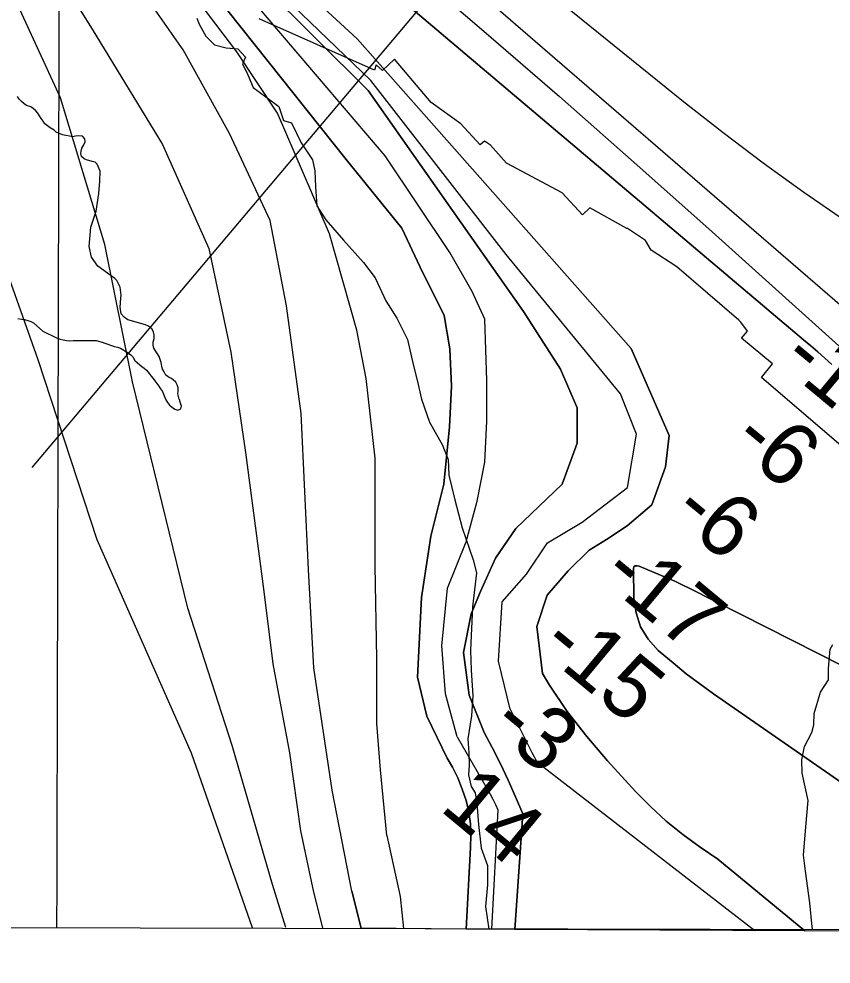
# Model space of a CAD drawing. Extents: x 3172231 to 3210228, y 940198 to 965780.
# Drawn here: x 3192098 to 3192968, y 945652 to 946666 of the extents above; entities that cross this region are included whole.
import ezdxf

# ---------------------------------------------------------------- set-up
doc = ezdxf.new("R2010")
doc.units = 0
for name, color, linetype in [('V-GRID-FRAM', 7, 'Continuous'), ('V-GRID-MAJR', 7, 'Continuous'), ('V-RIVR-EDGE', 7, 'Continuous'), ('V-RIVR-RANG', 7, 'Continuous'), ('V-RRAP-RVMT', 7, 'Continuous'), ('V-TOPO-DPTH', 7, 'Continuous'), ('V-TOPO-MAJR', 7, 'Continuous'), ('V-TOPO-MINR', 7, 'Continuous'), ('V-TOPO-SHOR', 7, 'Continuous'), ('V-TOPO-WATR', 7, 'Continuous')]:
    doc.layers.add(name, color=color, linetype=linetype)

msp = doc.modelspace()

# ---------------------------------------------------------------- linework, layer by layer
at = {"layer": 'V-GRID-FRAM'}
msp.add_lwpolyline([(3176539.592, 963919.479), (3207827.662, 963842.116), (3207790.623, 945652.442), (3176486.679, 945729.845), (3176539.592, 963919.479)], dxfattribs=at)
at = {"layer": 'V-GRID-MAJR'}
msp.add_spline([(3192138.65, 945691.144), (3192153.634, 951750.897), (3192168.626, 957814.116), (3192183.618, 963877.385), (3192183.626, 963880.798)], degree=3, dxfattribs=at)
at = {"layer": 'V-RIVR-EDGE'}
for points in [[(3192288.478, 946666.525), (3192291.056, 946660.295), (3192298.284, 946647.311), (3192307.597, 946637.953), (3192320.036, 946634.811), (3192332.48, 946633.742), (3192340.756, 946624.905), (3192337.626, 946617.652), (3192343.302, 946605.71), (3192348.973, 946592.212), (3192362.433, 946582.325), (3192376.41, 946571.918), (3192381.559, 946556.865), (3192389.851, 946554.251), (3192400.17, 946532.962), (3192412.572, 946514.78), (3192415.136, 946502.845), (3192415.612, 946485.729), (3192417.118, 946465.499), (3192426.935, 946450.435), (3192445.551, 946428.607), (3192467.274, 946404.697), (3192479.68, 946388.07), (3192491.029, 946363.667), (3192502.911, 946344.967), (3192514.265, 946322.119), (3192520.421, 946295.136), (3192524.529, 946278.53), (3192529.147, 946258.292), (3192537.902, 946233.376), (3192551.327, 946209.487), (3192558.029, 946193.393), (3192558.507, 946176.796), (3192565.184, 946150.329), (3192572.888, 946120.23), (3192584.732, 946085.972), (3192588.328, 946071.96), (3192584.089, 946035.667), (3192581.899, 945988.996), (3192582.365, 945967.732), (3192584.372, 945940.24), (3192582.762, 945918.461), (3192579.071, 945894.095), (3192580.071, 945879.053), (3192580.557, 945865.567), (3192579.494, 945855.197), (3192582.575, 945842.743), (3192586.707, 945835.991), (3192588.753, 945824.576)], [(3192948.613, 945689.141), (3192947.997, 945692.352), (3192945.439, 945718.247), (3192940.935, 945752.012), (3192938.684, 945769.386), (3192941.052, 945799.529), (3192943.744, 945827.706), (3192937.262, 945857.215), (3192936.97, 945871.307), (3192939.627, 945885.72), (3192947.529, 945900.775), (3192949.843, 945908.962), (3192950.201, 945921.086), (3192956.812, 945944.009), (3192965.365, 945957.096), (3192965.395, 945969.221), (3192967.085, 945990.19), (3192970.046, 945995.099)], [(3192588.753, 945824.576), (3192590.254, 945802.271), (3192593.303, 945776.851), (3192599.999, 945758.164), (3192599.948, 945737.42), (3192597.815, 945714.087), (3192601.342, 945689.999)]]:
    msp.add_lwpolyline(points, dxfattribs=at)
at = {"layer": 'V-RIVR-RANG'}
msp.add_line((3192112.067, 946184.869), (3192859.884, 947071.645), dxfattribs=at)
at = {"layer": 'V-RRAP-RVMT'}
for p, q in [((3192478.821, 946610.848), (3192355.33, 946665.852)), ((3192480.808, 946616.733), (3192478.821, 946610.848)), ((3192487.36, 946610.543), (3192480.808, 946616.733)), ((3192500.377, 946622.817), (3192487.36, 946610.543)), ((3192539.838, 946576.049), (3192500.377, 946622.817)), ((3192571.316, 946553.328), (3192539.838, 946576.049)), ((3192592.062, 946530.656), (3192571.316, 946553.328)), ((3192596.835, 946534.908), (3192592.062, 946530.656)), ((3192603.206, 946530.31), (3192596.835, 946534.908)), ((3192620.408, 946511.321), (3192603.206, 946530.31)), ((3192680.002, 946479.313), (3192620.408, 946511.321)), ((3192701.88, 946455.943), (3192680.002, 946479.313)), ((3192709.653, 946463.137), (3192701.88, 946455.943)), ((3192749.343, 946441.175), (3192709.653, 946463.137)), ((3192749.941, 946441.093), (3192749.343, 946441.175)), ((3192769.397, 946428.144), (3192749.941, 946441.093)), ((3192775.263, 946417.873), (3192769.397, 946428.144)), ((3192802.884, 946399.94), (3192775.263, 946417.873)), ((3192869.381, 946342.909), (3192802.884, 946399.94)), ((3192871.433, 946340.598), (3192869.381, 946342.909)), ((3192878.627, 946331.194), (3192871.433, 946340.598)), ((3192872.105, 946323.62), (3192878.627, 946331.194)), ((3192905.45, 946295.909), (3192872.105, 946323.62)), ((3192893.825, 946281.26), (3192905.45, 946295.909)), ((3192999.594, 946190.219), (3192893.825, 946281.26))]:
    msp.add_line(p, q, dxfattribs=at)
at = {"layer": 'V-TOPO-DPTH'}
for points in [[(3192099.681, 947031.915), (3192938.779, 946321.755), (3192946.371, 946315.27), (3192953.923, 946308.738), (3192961.414, 946302.136), (3192968.865, 946295.488)], [(3192968.865, 946295.488), (3192961.414, 946302.136), (3192953.923, 946308.738), (3192946.371, 946315.27), (3192938.779, 946321.755), (3192099.681, 947031.915)], [(3192125.015, 946953.462), (3192460.326, 946644.437), (3192753.916, 946312.397), (3192794.718, 946219.197), (3192790.938, 946185.676), (3192775.977, 946144.723), (3192749.876, 946122.415), (3192727.511, 946107.551), (3192708.876, 946096.406), (3192686.499, 946074.092), (3192664.115, 946048.052), (3192652.89, 946014.543), (3192658.947, 945963.859)], [(3192658.947, 945963.859), (3192652.89, 946014.543), (3192664.115, 946048.052), (3192686.499, 946074.092), (3192708.876, 946096.406), (3192727.511, 946107.551), (3192749.876, 946122.415), (3192775.977, 946144.723), (3192790.938, 946185.676), (3192794.718, 946219.197), (3192753.916, 946312.397), (3192460.326, 946644.437), (3192125.015, 946953.462)], [(3192556.965, 945873.249), (3192535.012, 945918.306), (3192525.143, 945960.083), (3192529.261, 946045.586), (3192539.308, 946111.193), (3192553.314, 946166.851), (3192559.38, 946228.487), (3192561.44, 946272.233), (3192559.519, 946312.008), (3192553.616, 946347.813), (3192527.864, 946399.56), (3192508.058, 946441.353), (3192448.554, 946515.031), (3192238.314, 946779.866), (3192074.996, 946940.791)], [(3192074.996, 946940.791), (3192238.314, 946779.866), (3192448.554, 946515.031), (3192508.058, 946441.353), (3192527.864, 946399.56), (3192553.616, 946347.813), (3192559.519, 946312.008), (3192561.44, 946272.233), (3192559.38, 946228.487), (3192553.314, 946166.851), (3192539.308, 946111.193), (3192529.261, 946045.586), (3192525.143, 945960.083), (3192535.012, 945918.306), (3192556.965, 945873.249)], [(3192596.457, 945900.913), (3192580.371, 945940.634), (3192574.484, 945986.382), (3192582.504, 946028.129), (3192592.482, 946051.975), (3192608.442, 946087.744), (3192630.358, 946119.525), (3192680.127, 946167.168), (3192696.1, 946210.891), (3192696.163, 946248.674), (3192678.345, 946290.465), (3192638.696, 946352.178), (3192581.193, 946433.806), (3192472.136, 946589.099), (3192245.929, 946814.188), (3192105.596, 946941.56)], [(3192105.596, 946941.56), (3192245.929, 946814.188), (3192472.136, 946589.099), (3192581.193, 946433.806), (3192638.696, 946352.178), (3192678.345, 946290.465), (3192696.163, 946248.674), (3192696.1, 946210.891), (3192680.127, 946167.168), (3192630.358, 946119.525), (3192608.442, 946087.744), (3192592.482, 946051.975), (3192582.504, 946028.129), (3192574.484, 945986.382), (3192580.371, 945940.634), (3192596.457, 945900.913)], [(3192454.597, 945730.763), (3192433.513, 945838.931), (3192413.857, 945970.211), (3192408.07, 946075.617), (3192400.398, 946242.672), (3192384.69, 946358.038), (3192366.954, 946449.543), (3192323.384, 946543.08), (3192273.844, 946632.65), (3192148.926, 946811.832), (3192048.178, 946936.112)], [(3192514.85, 946722.415), (3192596.158, 946652.773), (3192677.068, 946582.674), (3192757.379, 946511.89), (3192837.292, 946440.65), (3192980.139, 946312.212)], [(3192514.85, 946722.415), (3192596.158, 946652.773), (3192677.068, 946582.674), (3192757.379, 946511.89), (3192837.292, 946440.65), (3192980.139, 946312.212)], [(3193145.537, 945888.667), (3192816.049, 946055.524), (3192808.497, 946059.238), (3192800.889, 946062.833), (3192793.2, 946066.249), (3192785.456, 946069.546), (3192762.405, 946079.042), (3192760.407, 946079.509), (3192758.365, 946079.32), (3192756.889, 946078.336), (3192756.338, 946076.65), (3192756.928, 946044.903), (3192759.303, 946028.921), (3192764.055, 946014.045), (3192772.372, 946000.827), (3192783.065, 945988.714), (3192784.988, 945987.033), (3192798.885, 945975.27), (3192813.024, 945963.816), (3192827.526, 945952.826), (3192842.27, 945942.144), (3193028.61, 945812.751)], [(3193028.61, 945812.751), (3192842.27, 945942.144), (3192827.526, 945952.826), (3192813.024, 945963.816), (3192798.885, 945975.27), (3192784.988, 945987.033), (3192783.065, 945988.714), (3192772.372, 946000.827), (3192764.055, 946014.045), (3192759.303, 946028.921), (3192756.928, 946044.903), (3192756.338, 946076.65), (3192756.889, 946078.336), (3192758.365, 946079.32), (3192760.407, 946079.509), (3192762.405, 946079.042), (3192785.456, 946069.546), (3192793.2, 946066.249), (3192800.889, 946062.833), (3192808.497, 946059.238), (3192816.049, 946055.524), (3193145.537, 945888.667)], [(3192658.947, 945963.859), (3192666.543, 945951.383), (3192685.533, 945923.18), (3192706.414, 945896.347), (3192728.556, 945870.428), (3192758.571, 945837.649), (3192774.681, 945821.255), (3192791.495, 945805.676), (3192809.363, 945791.318), (3192827.934, 945777.775), (3192847.033, 945764.842), (3192939.958, 945688.192)], [(3192939.958, 945688.192), (3192847.033, 945764.842), (3192827.934, 945777.775), (3192809.363, 945791.318), (3192791.495, 945805.676), (3192774.681, 945821.255), (3192758.571, 945837.649), (3192728.556, 945870.428), (3192706.414, 945896.347), (3192685.533, 945923.18), (3192666.543, 945951.383), (3192658.947, 945963.859)], [(3192939.958, 945688.192), (3192629.237, 945689.446), (3192637.741, 945813.497), (3192630.198, 945831.613), (3192622.281, 945849.557), (3192613.802, 945867.242), (3192604.948, 945884.755), (3192596.457, 945900.913)], [(3192596.457, 945900.913), (3192604.948, 945884.755), (3192613.802, 945867.242), (3192622.281, 945849.557), (3192630.198, 945831.613), (3192637.741, 945813.497), (3192629.237, 945689.446)], [(3192629.237, 945689.446), (3192577.139, 945690.059), (3192581.784, 945777.451), (3192582.244, 945790.242), (3192581.757, 945802.943), (3192579.852, 945815.51), (3192577.002, 945827.988), (3192572.925, 945840.175), (3192568.197, 945852.071), (3192562.493, 945863.531), (3192556.965, 945873.249)], [(3192556.965, 945873.249), (3192562.493, 945863.531), (3192568.197, 945852.071), (3192572.925, 945840.175), (3192577.002, 945827.988), (3192579.852, 945815.51), (3192581.757, 945802.943), (3192582.244, 945790.242), (3192581.784, 945777.451), (3192577.139, 945690.059)], [(3192577.139, 945690.059), (3192464.738, 945690.822), (3192454.597, 945730.763)], [(3193216.424, 945687.024), (3192939.958, 945688.192)]]:
    msp.add_lwpolyline(points, dxfattribs=at)
at = {"layer": 'V-TOPO-MAJR'}
for points in [[(3191965.03, 946881.133), (3192003.878, 946837.926), (3192011.775, 946806.095), (3192015.704, 946778.248), (3192015.631, 946734.499), (3192017.539, 946686.769), (3192043.148, 946549.513), (3192070.782, 946434.128), (3192118.261, 946300.812), (3192181.541, 946107.812), (3192282.525, 945878.955), (3192347.711, 945691.839)], [(3192985.427, 946352.41), (3192545.757, 946733.188)]]:
    msp.add_lwpolyline(points, dxfattribs=at)
at = {"layer": 'V-TOPO-MINR'}
for points in [[(3192167.133, 947097.133), (3192810.081, 946577.224), (3192852.443, 946543.901), (3192895.379, 946511.356), (3192939.175, 946479.978), (3192983.545, 946449.379)], [(3192099.681, 947031.915), (3192938.779, 946321.755), (3192946.371, 946315.27), (3192953.923, 946308.738), (3192961.414, 946302.136), (3192968.865, 946295.488)], [(3192624.36, 945925.872), (3192611.871, 945977.359), (3192615.7, 946040.682), (3192641.813, 946070.441), (3192664.209, 946103.931), (3192701.479, 946126.221), (3192749.945, 946163.393), (3192759.718, 946220.728), (3192742.666, 946263.987), (3192620.044, 946413.203), (3192475.145, 946599.709), (3192289.277, 946778.832), (3192107.839, 946954.941)], [(3192658.947, 945963.859), (3192652.89, 946014.543), (3192664.115, 946048.052), (3192686.499, 946074.092), (3192708.876, 946096.406), (3192727.511, 946107.551), (3192749.876, 946122.415), (3192775.977, 946144.723), (3192790.938, 946185.676), (3192794.718, 946219.197), (3192753.916, 946312.397), (3192460.326, 946644.437), (3192125.015, 946953.462)], [(3192567.388, 945896.273), (3192554.927, 945942.136), (3192551.038, 945993.846), (3192557.104, 946055.482), (3192577.062, 946105.164), (3192589.06, 946148.894), (3192597.08, 946190.641), (3192599.141, 946234.387), (3192599.214, 946278.136), (3192597.336, 946343.763), (3192583.472, 946373.615), (3192559.691, 946415.415), (3192490.299, 946518.938), (3192303.833, 946737.996), (3192090.281, 946941.191)], [(3192596.457, 945900.913), (3192580.371, 945940.634), (3192574.484, 945986.382), (3192582.504, 946028.129), (3192592.482, 946051.975), (3192608.442, 946087.744), (3192630.358, 946119.525), (3192680.127, 946167.168), (3192696.1, 946210.891), (3192696.163, 946248.674), (3192678.345, 946290.465), (3192638.696, 946352.178), (3192581.193, 946433.806), (3192472.136, 946589.099), (3192245.929, 946814.188), (3192105.596, 946941.56)], [(3192454.597, 945730.763), (3192433.513, 945838.931), (3192413.857, 945970.211), (3192408.07, 946075.617), (3192400.398, 946242.672), (3192384.69, 946358.038), (3192366.954, 946449.543), (3192323.384, 946543.08), (3192273.844, 946632.65), (3192148.926, 946811.832), (3192048.178, 946936.112)], [(3192492.143, 945790.417), (3192485.226, 945860.719), (3192481.334, 945910.441), (3192481.45, 945980.042), (3192479.629, 946079.475), (3192479.821, 946194.814), (3192470.026, 946280.34), (3192460.174, 946332.06), (3192430.533, 946435.517), (3192375.097, 946564.868), (3192331.48, 946630.565), (3192256.119, 946730.121), (3192176.759, 946815.763), (3192063.442, 946936.674)], [(3192012.814, 946887.224), (3192093.235, 946788.062), (3192176.49, 946654.687), (3192251.812, 946531.268), (3192301.315, 946419.823), (3192324.98, 946308.422), (3192340.702, 946201.011), (3192360.329, 946051.833), (3192370.137, 945974.261), (3192387.866, 945878.779), (3192399.652, 945795.238), (3192413.455, 945729.591), (3192423.115, 945691.168)], [(3192384.031, 945691.507), (3192369.742, 945737.618), (3192326.265, 945886.836), (3192278.809, 946034.072), (3192219.587, 946276.78), (3192190.019, 946423.986), (3192142.579, 946581.165), (3192095.05, 946684.652), (3192051.516, 946800.063), (3192025.744, 946839.878), (3191992.769, 946879.29)], [(3192514.85, 946722.415), (3192596.158, 946652.773), (3192677.068, 946582.674), (3192757.379, 946511.89), (3192837.292, 946440.65), (3192980.139, 946312.212)], [(3193145.537, 945888.667), (3192816.049, 946055.524), (3192808.497, 946059.238), (3192800.889, 946062.833), (3192793.2, 946066.249), (3192785.456, 946069.546), (3192762.405, 946079.042), (3192760.407, 946079.509), (3192758.365, 946079.32), (3192756.889, 946078.336), (3192756.338, 946076.65), (3192756.928, 946044.903), (3192759.303, 946028.921), (3192764.055, 946014.045), (3192772.372, 946000.827), (3192783.065, 945988.714), (3192784.988, 945987.033), (3192798.885, 945975.27), (3192813.024, 945963.816), (3192827.526, 945952.826), (3192842.27, 945942.144), (3193028.61, 945812.751)], [(3192658.947, 945963.859), (3192666.543, 945951.383), (3192685.533, 945923.18), (3192706.414, 945896.347), (3192728.556, 945870.428), (3192758.571, 945837.649), (3192774.681, 945821.255), (3192791.495, 945805.676), (3192809.363, 945791.318), (3192827.934, 945777.775), (3192847.033, 945764.842), (3192939.958, 945688.192)], [(3192624.36, 945925.872), (3192631.851, 945910.893), (3192637.596, 945899.452), (3192642.649, 945889.393), (3192647.704, 945879.335), (3192652.762, 945869.279), (3192886.564, 945688.567)], [(3192596.457, 945900.913), (3192604.948, 945884.755), (3192613.802, 945867.242), (3192622.281, 945849.557), (3192630.198, 945831.613), (3192637.741, 945813.497), (3192629.237, 945689.446)], [(3192567.388, 945896.273), (3192599.807, 945840.225), (3192602.838, 945834.774), (3192605.745, 945829.259), (3192608.464, 945823.649), (3192611.057, 945817.976), (3192604.262, 945689.75)], [(3192492.143, 945790.417), (3192506.403, 945724.923), (3192510.014, 945690.468)], [(3192454.597, 945730.763), (3192464.738, 945690.822)]]:
    msp.add_lwpolyline(points, dxfattribs=at)
at = {"layer": 'V-TOPO-SHOR'}
for points in [[(3192185.071, 946502.59), (3192181.9, 946510.092), (3192179.514, 946512.176), (3192176.289, 946513.063), (3192170.442, 946514.622), (3192167.632, 946515.906), (3192165.049, 946518.198), (3192164.101, 946521.061), (3192164.578, 946524.092), (3192165.465, 946527.317), (3192167.378, 946530.924), (3192168.869, 946533.932), (3192168.623, 946537.359), (3192165.975, 946540.289), (3192161.719, 946540.592), (3192158.666, 946540.056), (3192155.604, 946539.317), (3192144.541, 946541.516), (3192137.87, 946544.4), (3192135.484, 946546.485), (3192131.493, 946549.215), (3192128.499, 946551.314), (3192125.707, 946553.409), (3192123.741, 946556.092), (3192121.779, 946558.977), (3192118.265, 946564.743), (3192116.09, 946567.227), (3192113.309, 946569.727), (3192110.509, 946571.417), (3192106.085, 946573.143), (3192103.488, 946574.827), (3192100.705, 946577.327), (3192098.127, 946579.822), (3192096.37, 946582.703)], [(3192259.411, 946251.632), (3192262.401, 946249.328), (3192264.994, 946247.442), (3192268.213, 946246.352), (3192271.289, 946247.7), (3192271.969, 946250.727), (3192270.847, 946254.81), (3192270.47, 946256.037), (3192270.282, 946256.65), (3192269.901, 946257.674), (3192269.712, 946258.288), (3192268.967, 946261.145), (3192268.223, 946264.002), (3192268.494, 946266.836), (3192268.545, 946269.067), (3192268.371, 946270.287), (3192267.429, 946273.353), (3192265.872, 946276.231), (3192263.294, 946278.725), (3192260.498, 946280.617), (3192257.693, 946282.102), (3192255.303, 946283.984), (3192253.351, 946287.277), (3192251.598, 946290.362), (3192250.858, 946293.421), (3192250.138, 946297.294), (3192249.206, 946300.764), (3192248.065, 946304.036), (3192246.302, 946306.715), (3192244.143, 946309.81), (3192242.587, 946312.687), (3192241.651, 946315.956), (3192241.731, 946319.402), (3192242.632, 946323.234), (3192242.714, 946326.683), (3192241.989, 946330.351), (3192240.24, 946333.638), (3192236.656, 946336.563), (3192233.44, 946337.857), (3192214.5, 946343.372), (3192210.595, 946345.901), (3192207.289, 946349.784), (3192206.228, 946356.739), (3192206.923, 946366.273), (3192207.609, 946369.503), (3192206.22, 946378.286), (3192202.911, 946385.438), (3192200.525, 946387.523), (3192182.552, 946400.583), (3192175.715, 946410.528), (3192172.987, 946421.737), (3192175.107, 946442.616), (3192180.532, 946459.615), (3192183.561, 946478.706), (3192184.415, 946492.006), (3192185.071, 946502.59)], [(3192096.66, 946344.722), (3192100.498, 946344.023), (3192103.732, 946343.54), (3192107.363, 946342.643), (3192110.788, 946341.549), (3192113.587, 946339.862), (3192123.44, 946331.16), (3192137.967, 946324.072), (3192142.192, 946322.552), (3192145.214, 946321.669), (3192148.85, 946320.975), (3192152.09, 946320.697), (3192155.956, 946321.215), (3192180.702, 946321.039), (3192186.951, 946319.269), (3192189.767, 946318.188), (3192200.234, 946314.696), (3192203.464, 946314.012), (3192206.679, 946312.72), (3192215.084, 946307.856), (3192217.669, 946305.564), (3192219.852, 946303.483), (3192222.199, 946299.776), (3192224.773, 946297.077), (3192227.362, 946294.988), (3192229.752, 946293.106), (3192232.142, 946291.224), (3192234.528, 946289.139), (3192237.487, 946285.621), (3192239.453, 946282.938), (3192241.626, 946280.451), (3192243.596, 946277.971), (3192245.761, 946275.08), (3192247.717, 946271.991), (3192249.476, 946269.11), (3192251.645, 946266.421), (3192252.79, 946263.351), (3192255.286, 946257.409), (3192257.05, 946254.731), (3192259.411, 946251.632)]]:
    msp.add_lwpolyline(points, dxfattribs=at)
at = {"layer": 'V-TOPO-WATR'}
for points in [[(3192556.965, 945873.249), (3192535.012, 945918.306), (3192525.143, 945960.083), (3192529.261, 946045.586), (3192539.308, 946111.193), (3192553.314, 946166.851), (3192559.38, 946228.487), (3192561.44, 946272.233), (3192559.519, 946312.008), (3192553.616, 946347.813), (3192527.864, 946399.56), (3192508.058, 946441.353), (3192448.554, 946515.031), (3192238.314, 946779.866), (3192074.996, 946940.791)], [(3192556.965, 945873.249), (3192562.493, 945863.531), (3192568.197, 945852.071), (3192572.925, 945840.175), (3192577.002, 945827.988), (3192579.852, 945815.51), (3192581.757, 945802.943), (3192582.244, 945790.242), (3192581.784, 945777.451), (3192577.139, 945690.059)]]:
    msp.add_lwpolyline(points, dxfattribs=at)

# ---------------------------------------------------------------- texts
at = {"layer": 'V-RIVR-RANG'}
for s, p in [('-14', (3192911.494, 946295.95)), ('-6', (3192859, 946209.55)), ('-6', (3192794.943, 946132.76)), ('-17', (3192719.122, 946065.749)), ('-15', (3192653.847, 945989.97)), ('-3', (3192600.339, 945904.412)), ('14', (3192547.44, 945818.348))]:
    msp.add_text(s, height=67, rotation=320.268889, dxfattribs=at).set_placement(p)

doc.saveas('drawing.dxf')
